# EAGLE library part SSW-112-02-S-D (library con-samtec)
THROUGH-HOLE .025" SQ POST SOCKET Source: Samtec SSW.pdf
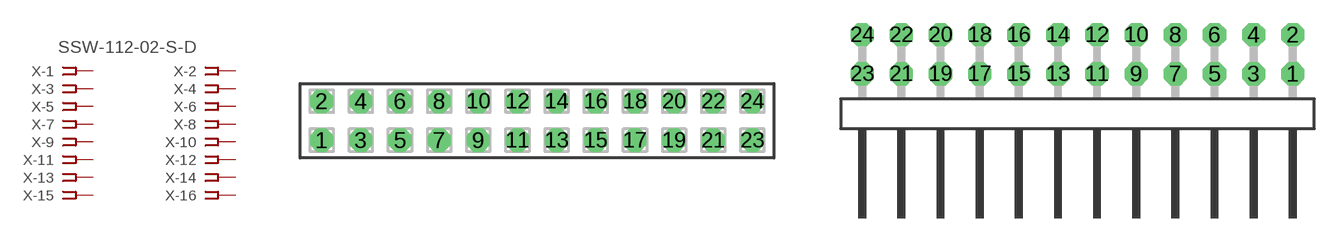
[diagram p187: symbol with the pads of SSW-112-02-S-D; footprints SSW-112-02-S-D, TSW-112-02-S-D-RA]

Designator prefix X; gates -1=FPINV -2=FPIN -3=FPIN -4=FPIN -5=FPIN -6=FPIN -7=FPIN -8=FPIN -9=FPIN -10=FPIN -11=FPIN -12=FPIN -13=FPIN -14=FPIN -15=FPIN -16=FPIN -17=FPIN -18=FPIN -19=FPIN -20=FPIN -21=FPIN -22=FPIN -23=FPIN -24=FPIN

## SSW-112-02-S-D (MPN: SSW-112-02-S-D; OC_FARNELL: unknown; OC_NEWARK: 11P9513)  [SSW-112-02-S-D]
1  -1:1  pas
2  -2:1  pas
3  -3:1  pas
4  -4:1  pas
5  -5:1  pas
6  -6:1  pas
7  -7:1  pas
8  -8:1  pas
9  -9:1  pas
10  -10:1  pas
11  -11:1  pas
12  -12:1  pas
13  -13:1  pas
14  -14:1  pas
15  -15:1  pas
16  -16:1  pas
17  -17:1  pas
18  -18:1  pas
19  -19:1  pas
20  -20:1  pas
21  -21:1  pas
22  -22:1  pas
23  -23:1  pas
24  -24:1  pas

## SSW-112-02-S-D-RA (MPN: SSW-112-02-S-D-RA; OC_FARNELL: unknown; OC_NEWARK: 11P9514)  [TSW-112-02-S-D-RA]
Pads as for SSW-112-02-S-D

## Footprint SSW-112-02-S-D (pad centres in mm)
THROUGH-HOLE .025" SQ POST SOCKET Source: Samtec SSW.pdf
drill 1 pad 1.5 octagon: 1 -13.97,-1.27; 2 -13.97,1.27; 3 -11.43,-1.27; 4 -11.43,1.27; 5 -8.89,-1.27; 6 -8.89,1.27; 7 -6.35,-1.27; 8 -6.35,1.27; 9 -3.81,-1.27; 10 -3.81,1.27; 11 -1.27,-1.27; 12 -1.27,1.27; 13 1.27,-1.27; 14 1.27,1.27; 15 3.81,-1.27; 16 3.81,1.27; 17 6.35,-1.27; 18 6.35,1.27; 19 8.89,-1.27; 20 8.89,1.27; 21 11.43,-1.27; 22 11.43,1.27; 23 13.97,-1.27; 24 13.97,1.27

## Footprint TSW-112-02-S-D-RA (pad centres in mm)
THROUGH-HOLE .025" SQ POST HEADER Source: Samtec TSW.pdf
drill 1 pad 1.5 octagon: 1 13.97,1.524; 2 13.97,4.064; 3 11.43,1.524; 4 11.43,4.064; 5 8.89,1.524; 6 8.89,4.064; 7 6.35,1.524; 8 6.35,4.064; 9 3.81,1.524; 10 3.81,4.064; 11 1.27,1.524; 12 1.27,4.064; 13 -1.27,1.524; 14 -1.27,4.064; 15 -3.81,1.524; 16 -3.81,4.064; 17 -6.35,1.524; 18 -6.35,4.064; 19 -8.89,1.524; 20 -8.89,4.064; 21 -11.43,1.524; 22 -11.43,4.064; 23 -13.97,1.524; 24 -13.97,4.064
